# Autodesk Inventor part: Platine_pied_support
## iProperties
Shininess: 64.0
Length Units: 11269
Angle Units: 11279
Time Units: 11290
Mass Units: 11283
Length Display Precision: 3
Angle Display Precision: 2
Compacted: True
Part Number: Platine_pied_support
Document SubType Name: Modeling
Created: 2008-03
Material: Par défaut
Designer: Pascal
Density: 0.0
Volumn: 0.0
Area: 0.0
PropertySet Name: Model Information
Control State: 0
Master: False
Checked Out: False
DESIGNATION: pièce
Author: Pascal
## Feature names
1. Extrusion1
2. Congé1 [Fillet]
3. Extrusion2
4. Réseau rectangulaire1 [Rectangular Pattern]
